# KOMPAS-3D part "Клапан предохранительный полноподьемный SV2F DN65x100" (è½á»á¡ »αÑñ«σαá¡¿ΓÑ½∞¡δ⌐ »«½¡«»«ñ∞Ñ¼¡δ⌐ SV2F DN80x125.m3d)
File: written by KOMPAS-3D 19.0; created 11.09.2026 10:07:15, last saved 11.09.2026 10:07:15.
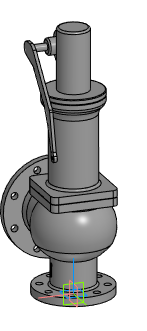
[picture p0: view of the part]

Document properties: Автор: Энергия; Полное имя файла: Z:\3.Личные\sachek\Dendor\_3D для проектировщиков\5.9 SV2F. Клапан предохранительный полноподьемный\SV2F_STP\Клапан предохранительный полноподьемный SV2F DN80x125.m3d

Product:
- Part/product: Клапан предохранительный полноподьемный SV2F DN65x100

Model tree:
1. Операция без истории:1  (labels: Клапан предохранительный полноподьемный SV2F DN65x100)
